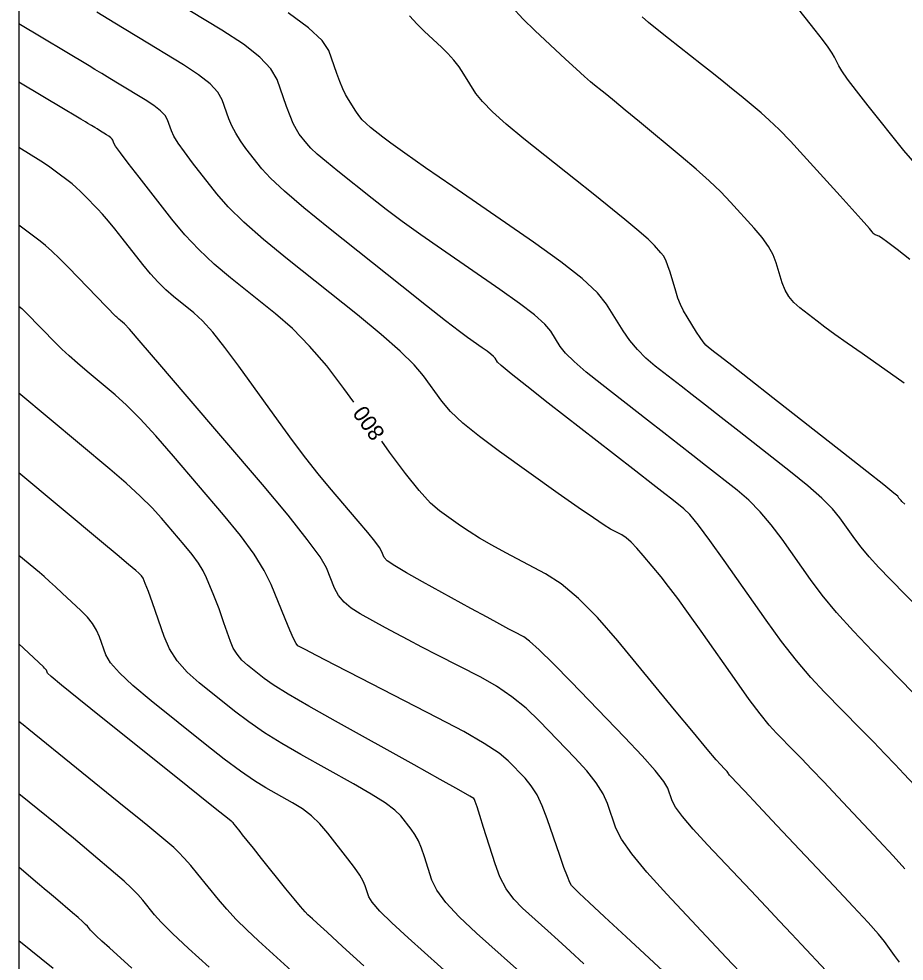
# Model space of a CAD drawing. Extents: x 2082232 to 2083549, y 592624 to 593832.
# Drawn here: x 2082231.79 to 2082270.56, y 593384.11 to 593425.39 of the extents above; entities that cross this region are included whole.
import ezdxf

# ---------------------------------------------------------------- set-up
doc = ezdxf.new("R2010")
doc.units = 0
for name, color, linetype in [('DT_X_Contour_Major', 7, 'Continuous'), ('DT_X_Contour_Minor', 7, 'Continuous'), ('DT_X_TIN_Hull', 7, 'Continuous')]:
    doc.layers.add(name, color=color, linetype=linetype)

msp = doc.modelspace()

# ---------------------------------------------------------------- linework, layer by layer
at = {"layer": 'DT_X_Contour_Major'}
for points in [[(2082270.584, 593404.122), (2082270.465, 593404.244), (2082270.423, 593404.288), (2082270.387, 593404.327), (2082270.357, 593404.363), (2082270.334, 593404.394), (2082270.279, 593404.472), (2082270.116, 593404.612), (2082269.666, 593404.972), (2082268.931, 593405.553), (2082267.91, 593406.355), (2082264.806, 593408.788), (2082263.775, 593409.597), (2082263.008, 593410.197), (2082262.507, 593410.59), (2082262.27, 593410.775), (2082261.993, 593410.991), (2082261.882, 593411.094), (2082261.758, 593411.24), (2082261.621, 593411.428), (2082261.471, 593411.66), (2082261.052, 593412.335), (2082260.903, 593412.596), (2082260.77, 593412.87), (2082260.654, 593413.159), (2082260.554, 593413.462), (2082260.309, 593414.288), (2082260.215, 593414.574), (2082260.117, 593414.812), (2082260.016, 593415.003), (2082259.91, 593415.145), (2082259.623, 593415.462), (2082259.5, 593415.59), (2082259.346, 593415.736), (2082259.161, 593415.901), (2082258.945, 593416.084), (2082258.327, 593416.596), (2082258.018, 593416.849), (2082257.555, 593417.223), (2082256.937, 593417.718), (2082256.166, 593418.334), (2082253.902, 593420.138), (2082253.134, 593420.77), (2082252.529, 593421.312), (2082252.087, 593421.763), (2082251.807, 593422.125), (2082251.278, 593422.97), (2082251.068, 593423.281), (2082250.837, 593423.579), (2082250.582, 593423.865), (2082250.306, 593424.138), (2082249.539, 593424.851), (2082249.236, 593425.154), (2082248.902, 593425.526)], [(2082246.452, 593408.59), (2082246.019, 593409.192), (2082245.269, 593410.18), (2082244.522, 593411.055), (2082243.777, 593411.816), (2082243.034, 593412.465), (2082241.055, 593414.043), (2082240.339, 593414.648), (2082239.673, 593415.277), (2082239.058, 593415.932), (2082238.493, 593416.612), (2082237.055, 593418.459), (2082236.581, 593419.072), (2082236.238, 593419.523), (2082236.025, 593419.813), (2082235.942, 593419.942), (2082235.896, 593420.073), (2082235.867, 593420.124), (2082235.813, 593420.181), (2082235.734, 593420.243), (2082235.631, 593420.311), (2082235.323, 593420.498), (2082235.214, 593420.564), (2082235.119, 593420.622), (2082235.038, 593420.671), (2082234.97, 593420.712), (2082234.807, 593420.81), (2082234.699, 593420.874), (2082234.497, 593420.995), (2082234.203, 593421.171), (2082233.815, 593421.403), (2082231.787, 593422.616)], [(2082270.363, 593384.065), (2082270.137, 593384.36), (2082269.698, 593384.96), (2082269.436, 593385.281), (2082268.982, 593385.795), (2082268.334, 593386.5), (2082267.492, 593387.398), (2082264.991, 593390.049), (2082264.166, 593390.924), (2082263.565, 593391.561), (2082263.19, 593391.958), (2082263.04, 593392.118), (2082262.939, 593392.225), (2082262.906, 593392.261), (2082262.881, 593392.291), (2082262.864, 593392.313), (2082262.856, 593392.327), (2082262.846, 593392.357), (2082262.834, 593392.376), (2082262.806, 593392.41), (2082262.76, 593392.459), (2082262.699, 593392.524), (2082262.511, 593392.718), (2082262.334, 593392.923), (2082261.94, 593393.391), (2082261.331, 593394.124), (2082260.507, 593395.121), (2082258.021, 593398.132), (2082257.124, 593399.163), (2082256.296, 593399.998), (2082255.539, 593400.637), (2082254.852, 593401.08), (2082253.114, 593402.001), (2082252.501, 593402.333), (2082251.965, 593402.641), (2082251.506, 593402.923), (2082251.124, 593403.18), (2082250.209, 593403.831), (2082249.815, 593404.175), (2082249.319, 593404.719), (2082248.721, 593405.463), (2082248.021, 593406.408), (2082247.678, 593406.885)], [(2082254.117, 593383.283), (2082251.833, 593385.333), (2082251.068, 593386.054), (2082250.487, 593386.68), (2082250.09, 593387.211), (2082249.876, 593387.647), (2082249.552, 593388.683), (2082249.424, 593389.05), (2082249.284, 593389.374), (2082249.132, 593389.656), (2082248.968, 593389.894), (2082248.515, 593390.474), (2082248.257, 593390.725), (2082247.826, 593391.041), (2082247.221, 593391.424), (2082246.441, 593391.873), (2082244.13, 593393.159), (2082243.299, 593393.639), (2082242.54, 593394.115), (2082241.853, 593394.586), (2082241.237, 593395.053), (2082239.691, 593396.292), (2082239.16, 593396.768), (2082238.726, 593397.266), (2082238.388, 593397.786), (2082238.148, 593398.329), (2082237.636, 593399.805), (2082237.462, 593400.294), (2082237.326, 593400.656), (2082237.226, 593400.889), (2082237.163, 593400.994), (2082237.046, 593401.104), (2082236.91, 593401.221), (2082236.592, 593401.489), (2082236.091, 593401.908), (2082235.406, 593402.479), (2082231.787, 593405.496)], [(2082236.733, 593383.805), (2082235.753, 593384.687), (2082235.426, 593384.984), (2082235.178, 593385.213), (2082235.009, 593385.376), (2082234.92, 593385.47), (2082234.789, 593385.633), (2082234.711, 593385.716), (2082234.576, 593385.843), (2082234.384, 593386.014), (2082234.134, 593386.228), (2082233.392, 593386.858), (2082233.129, 593387.081), (2082232.896, 593387.279), (2082232.693, 593387.451), (2082232.521, 593387.597), (2082231.787, 593388.22)]]:
    msp.add_lwpolyline(points, dxfattribs=at)
at = {"layer": 'DT_X_Contour_Minor'}
for points in [[(2082271.56, 593395.252), (2082269.177, 593397.682), (2082268.337, 593398.563), (2082267.603, 593399.381), (2082266.977, 593400.136), (2082266.458, 593400.83), (2082265.215, 593402.597), (2082264.742, 593403.227), (2082264.256, 593403.794), (2082263.757, 593404.298), (2082263.243, 593404.737), (2082261.857, 593405.824), (2082261.308, 593406.254), (2082260.701, 593406.728), (2082260.037, 593407.246), (2082259.316, 593407.808), (2082257.314, 593409.367), (2082256.638, 593409.91), (2082256.11, 593410.37), (2082255.731, 593410.746), (2082255.501, 593411.039), (2082255.086, 593411.708), (2082254.83, 593412.01), (2082254.373, 593412.415), (2082253.716, 593412.923), (2082252.857, 593413.534), (2082250.301, 593415.298), (2082249.392, 593415.933), (2082248.582, 593416.515), (2082247.871, 593417.043), (2082247.26, 593417.518), (2082245.762, 593418.713), (2082245.255, 593419.125), (2082244.858, 593419.464), (2082244.571, 593419.73), (2082244.394, 593419.923), (2082244.069, 593420.341), (2082243.942, 593420.534), (2082243.807, 593420.799), (2082243.664, 593421.136), (2082243.512, 593421.544), (2082243.097, 593422.729), (2082242.829, 593423.198), (2082242.337, 593423.716), (2082241.621, 593424.282), (2082240.682, 593424.897), (2082237.878, 593426.603)], [(2082271.516, 593391.292), (2082270.553, 593392.312), (2082270.164, 593392.723), (2082269.716, 593393.187), (2082269.212, 593393.707), (2082268.651, 593394.281), (2082267.077, 593395.886), (2082266.474, 593396.535), (2082265.847, 593397.278), (2082265.196, 593398.116), (2082264.519, 593399.048), (2082262.683, 593401.659), (2082262.056, 593402.535), (2082261.551, 593403.205), (2082261.169, 593403.67), (2082260.91, 593403.928), (2082260.382, 593404.342), (2082260.074, 593404.582), (2082259.548, 593404.993), (2082258.803, 593405.574), (2082257.838, 593406.325), (2082254.974, 593408.555), (2082254.03, 593409.295), (2082253.344, 593409.841), (2082252.917, 593410.195), (2082252.748, 593410.354), (2082252.644, 593410.523), (2082252.579, 593410.599), (2082252.465, 593410.701), (2082252.299, 593410.829), (2082252.083, 593410.982), (2082251.44, 593411.426), (2082251.079, 593411.691), (2082250.478, 593412.155), (2082249.636, 593412.816), (2082248.555, 593413.676), (2082245.352, 593416.232), (2082244.268, 593417.112), (2082243.42, 593417.837), (2082242.806, 593418.406), (2082242.427, 593418.819), (2082241.731, 593419.714), (2082241.489, 593420.047), (2082241.284, 593420.374), (2082241.118, 593420.695), (2082240.989, 593421.01), (2082240.697, 593421.844), (2082240.508, 593422.174), (2082240.162, 593422.538), (2082239.659, 593422.936), (2082238.998, 593423.369), (2082237.026, 593424.568), (2082236.33, 593424.991), (2082235.721, 593425.36), (2082235.199, 593425.675)], [(2082270.567, 593409.421), (2082268.715, 593410.722), (2082268.071, 593411.176), (2082267.53, 593411.564), (2082267.09, 593411.884), (2082266.753, 593412.138), (2082265.989, 593412.724), (2082265.727, 593412.958), (2082265.511, 593413.219), (2082265.343, 593413.508), (2082265.221, 593413.824), (2082264.961, 593414.703), (2082264.826, 593415.045), (2082264.62, 593415.412), (2082264.341, 593415.803), (2082263.989, 593416.219), (2082262.954, 593417.361), (2082262.528, 593417.807), (2082262.028, 593418.289), (2082261.452, 593418.806), (2082260.802, 593419.359), (2082258.967, 593420.881), (2082258.349, 593421.393), (2082257.872, 593421.787), (2082257.535, 593422.063), (2082257.338, 593422.221), (2082257.002, 593422.484), (2082256.828, 593422.63), (2082256.559, 593422.868), (2082256.195, 593423.199), (2082255.736, 593423.624), (2082254.385, 593424.879), (2082253.877, 593425.378), (2082253.367, 593425.931)], [(2082271.131, 593418.944), (2082270.54, 593419.617), (2082268.992, 593421.571), (2082268.476, 593422.23), (2082268.087, 593422.742), (2082267.826, 593423.107), (2082267.693, 593423.325), (2082267.507, 593423.71), (2082267.403, 593423.892), (2082267.227, 593424.149), (2082266.981, 593424.48), (2082266.665, 593424.887), (2082265.726, 593426.07)], [(2082271.361, 593399.393), (2082269.945, 593400.837), (2082269.449, 593401.354), (2082269.026, 593401.822), (2082268.675, 593402.242), (2082268.396, 593402.612), (2082267.747, 593403.534), (2082267.429, 593403.92), (2082266.961, 593404.383), (2082266.344, 593404.925), (2082265.577, 593405.546), (2082263.332, 593407.306), (2082262.541, 593407.925), (2082261.855, 593408.463), (2082261.272, 593408.918), (2082260.793, 593409.292), (2082259.653, 593410.179), (2082259.245, 593410.525), (2082258.876, 593410.898), (2082258.546, 593411.297), (2082258.254, 593411.723), (2082257.528, 593412.893), (2082257.124, 593413.392), (2082256.457, 593414.01), (2082255.525, 593414.747), (2082254.33, 593415.603), (2082250.79, 593418.046), (2082249.604, 593418.868), (2082248.698, 593419.501), (2082248.073, 593419.945), (2082247.73, 593420.202), (2082247.188, 593420.633), (2082246.995, 593420.799), (2082246.823, 593420.972), (2082246.672, 593421.153), (2082246.541, 593421.341), (2082246.221, 593421.853), (2082246.099, 593422.068), (2082245.974, 593422.33), (2082245.846, 593422.639), (2082245.714, 593422.996), (2082245.359, 593424.008), (2082245.072, 593424.444), (2082244.477, 593424.993), (2082243.575, 593425.653)], [(2082270.814, 593414.852), (2082270.253, 593415.282), (2082269.839, 593415.594), (2082269.573, 593415.788), (2082269.455, 593415.863), (2082269.338, 593415.908), (2082269.294, 593415.929), (2082269.251, 593415.961), (2082269.207, 593416.001), (2082269.163, 593416.052), (2082269.046, 593416.2), (2082268.932, 593416.331), (2082268.679, 593416.615), (2082268.287, 593417.05), (2082267.755, 593417.638), (2082266.151, 593419.408), (2082265.584, 593420.023), (2082265.085, 593420.539), (2082264.656, 593420.957), (2082264.297, 593421.276), (2082263.429, 593421.996), (2082263.076, 593422.285), (2082262.668, 593422.614), (2082262.206, 593422.982), (2082261.689, 593423.389), (2082260.237, 593424.526), (2082259.747, 593424.917), (2082259.364, 593425.236), (2082259.091, 593425.484)], [(2082270.596, 593388.148), (2082270.078, 593388.727), (2082269.457, 593389.396), (2082267.661, 593391.299), (2082267.036, 593391.96), (2082266.507, 593392.516), (2082266.076, 593392.966), (2082265.741, 593393.311), (2082264.977, 593394.09), (2082264.653, 593394.45), (2082264.254, 593394.945), (2082263.78, 593395.576), (2082263.231, 593396.342), (2082261.667, 593398.565), (2082261.118, 593399.339), (2082260.642, 593399.992), (2082260.24, 593400.526), (2082259.912, 593400.939), (2082259.135, 593401.88), (2082258.858, 593402.2), (2082258.608, 593402.457), (2082258.385, 593402.649), (2082258.19, 593402.777), (2082257.707, 593403.033), (2082257.427, 593403.203), (2082256.952, 593403.521), (2082256.28, 593403.986), (2082255.413, 593404.6), (2082252.837, 593406.433), (2082251.955, 593407.087), (2082251.239, 593407.673), (2082250.689, 593408.191), (2082250.306, 593408.641), (2082249.507, 593409.753), (2082249.102, 593410.232), (2082248.484, 593410.835), (2082247.655, 593411.563), (2082246.614, 593412.416), (2082243.555, 593414.857), (2082242.501, 593415.722), (2082241.634, 593416.487), (2082240.954, 593417.152), (2082240.46, 593417.716), (2082239.393, 593419.087), (2082239.035, 593419.559), (2082238.761, 593419.948), (2082238.571, 593420.254), (2082238.466, 593420.476), (2082238.296, 593420.958), (2082238.188, 593421.149), (2082237.988, 593421.359), (2082237.697, 593421.59), (2082237.315, 593421.84), (2082236.175, 593422.533), (2082235.772, 593422.777), (2082235.42, 593422.991), (2082235.118, 593423.173), (2082234.867, 593423.324), (2082231.787, 593425.167)], [(2082267.13, 593383.703), (2082266.06, 593384.838), (2082265.62, 593385.304), (2082265.103, 593385.853), (2082264.511, 593386.484), (2082263.841, 593387.197), (2082261.953, 593389.208), (2082261.325, 593389.893), (2082260.856, 593390.443), (2082260.546, 593390.855), (2082260.396, 593391.131), (2082260.207, 593391.685), (2082260.035, 593391.98), (2082259.662, 593392.451), (2082259.088, 593393.096), (2082258.312, 593393.916), (2082255.974, 593396.337), (2082255.188, 593397.141), (2082254.581, 593397.739), (2082254.153, 593398.13), (2082253.905, 593398.315), (2082253.484, 593398.532), (2082253.246, 593398.657), (2082252.849, 593398.87), (2082252.294, 593399.172), (2082251.579, 593399.562), (2082249.46, 593400.719), (2082248.76, 593401.112), (2082248.247, 593401.422), (2082247.923, 593401.649), (2082247.787, 593401.794), (2082247.676, 593402.07), (2082247.58, 593402.23), (2082247.377, 593402.502), (2082247.067, 593402.886), (2082246.649, 593403.383), (2082245.392, 593404.858), (2082244.899, 593405.454), (2082244.361, 593406.138), (2082243.779, 593406.909), (2082243.153, 593407.767), (2082241.423, 593410.172), (2082240.814, 593410.995), (2082240.282, 593411.659), (2082239.829, 593412.166), (2082239.453, 593412.513), (2082238.556, 593413.229), (2082238.22, 593413.518), (2082237.883, 593413.848), (2082237.547, 593414.218), (2082237.211, 593414.629), (2082236.315, 593415.78), (2082235.996, 593416.184), (2082235.709, 593416.532), (2082235.455, 593416.826), (2082235.235, 593417.064), (2082234.69, 593417.625), (2082234.49, 593417.825), (2082234.299, 593418.003), (2082234.117, 593418.161), (2082233.944, 593418.298), (2082233.494, 593418.635), (2082233.321, 593418.762), (2082233.139, 593418.89), (2082232.947, 593419.019), (2082232.746, 593419.149), (2082231.787, 593419.757)], [(2082263.654, 593383.332), (2082262.772, 593384.268), (2082260.166, 593387.044), (2082259.294, 593388.006), (2082258.631, 593388.808), (2082258.178, 593389.451), (2082257.935, 593389.935), (2082257.567, 593391.014), (2082257.374, 593391.442), (2082257.071, 593391.919), (2082256.659, 593392.444), (2082256.136, 593393.018), (2082254.597, 593394.613), (2082254.002, 593395.182), (2082253.375, 593395.693), (2082252.713, 593396.146), (2082252.017, 593396.541), (2082250.118, 593397.518), (2082249.442, 593397.867), (2082248.839, 593398.182), (2082248.309, 593398.463), (2082247.852, 593398.71), (2082246.73, 593399.322), (2082246.344, 593399.565), (2082246.031, 593399.834), (2082245.788, 593400.129), (2082245.618, 593400.45), (2082245.257, 593401.341), (2082244.981, 593401.819), (2082244.421, 593402.585), (2082243.579, 593403.639), (2082242.454, 593404.981), (2082239.077, 593408.943), (2082237.961, 593410.25), (2082237.145, 593411.199), (2082236.628, 593411.791), (2082236.412, 593412.025), (2082236.234, 593412.173), (2082236.172, 593412.226), (2082236.118, 593412.273), (2082236.073, 593412.315), (2082236.036, 593412.352), (2082233.955, 593414.495), (2082233.568, 593414.887), (2082233.235, 593415.209), (2082232.954, 593415.463), (2082232.726, 593415.648), (2082231.787, 593416.352)], [(2082261.21, 593382.55), (2082258.38, 593385.173), (2082257.444, 593386.041), (2082256.76, 593386.679), (2082256.327, 593387.085), (2082256.146, 593387.26), (2082255.997, 593387.418), (2082255.923, 593387.545), (2082255.811, 593387.808), (2082255.662, 593388.206), (2082255.475, 593388.739), (2082254.928, 593390.342), (2082254.713, 593390.904), (2082254.481, 593391.388), (2082254.23, 593391.793), (2082253.961, 593392.12), (2082253.219, 593392.889), (2082252.817, 593393.222), (2082252.168, 593393.646), (2082251.272, 593394.161), (2082250.129, 593394.767), (2082246.752, 593396.504), (2082245.638, 593397.077), (2082244.829, 593397.493), (2082244.324, 593397.753), (2082244.125, 593397.857), (2082243.999, 593397.926), (2082243.929, 593398.019), (2082243.814, 593398.247), (2082243.654, 593398.609), (2082243.448, 593399.107), (2082242.839, 593400.612), (2082242.537, 593401.226), (2082242.087, 593401.939), (2082241.489, 593402.752), (2082240.744, 593403.663), (2082238.559, 593406.226), (2082237.785, 593407.115), (2082237.101, 593407.86), (2082236.508, 593408.459), (2082236.005, 593408.914), (2082234.783, 593409.934), (2082234.354, 593410.298), (2082233.984, 593410.624), (2082233.671, 593410.913), (2082233.416, 593411.164), (2082232.092, 593412.528), (2082232.037, 593412.583), (2082231.99, 593412.629), (2082231.951, 593412.664), (2082231.919, 593412.69), (2082231.787, 593412.789)], [(2082256.532, 593383.989), (2082255.933, 593384.539), (2082255.408, 593385.019), (2082254.956, 593385.427), (2082253.85, 593386.42), (2082253.463, 593386.821), (2082253.133, 593387.279), (2082252.86, 593387.793), (2082252.644, 593388.365), (2082252.142, 593389.965), (2082251.976, 593390.492), (2082251.854, 593390.873), (2082251.777, 593391.107), (2082251.743, 593391.194), (2082251.714, 593391.232), (2082251.542, 593391.335), (2082251.05, 593391.613), (2082250.238, 593392.069), (2082249.104, 593392.7), (2082245.655, 593394.619), (2082244.489, 593395.276), (2082243.579, 593395.807), (2082242.925, 593396.213), (2082242.527, 593396.492), (2082241.806, 593397.07), (2082241.556, 593397.298), (2082241.348, 593397.548), (2082241.18, 593397.82), (2082241.053, 593398.115), (2082240.77, 593398.931), (2082240.663, 593399.235), (2082240.553, 593399.534), (2082240.44, 593399.83), (2082240.324, 593400.122), (2082240.012, 593400.894), (2082239.863, 593401.202), (2082239.65, 593401.546), (2082239.373, 593401.928), (2082239.033, 593402.346), (2082238.041, 593403.51), (2082237.62, 593403.972), (2082237.103, 593404.483), (2082236.488, 593405.043), (2082235.777, 593405.653), (2082231.787, 593408.986)], [(2082250.99, 593383.193), (2082248.835, 593385.126), (2082248.122, 593385.783), (2082247.596, 593386.302), (2082247.258, 593386.685), (2082247.109, 593386.93), (2082246.961, 593387.401), (2082246.872, 593387.608), (2082246.714, 593387.876), (2082246.487, 593388.205), (2082246.193, 593388.595), (2082245.315, 593389.716), (2082244.973, 593390.115), (2082244.602, 593390.469), (2082244.204, 593390.78), (2082243.778, 593391.047), (2082242.605, 593391.699), (2082242.109, 593392.003), (2082241.501, 593392.423), (2082240.78, 593392.96), (2082239.947, 593393.614), (2082237.576, 593395.514), (2082236.786, 593396.175), (2082236.192, 593396.73), (2082235.795, 593397.181), (2082235.594, 593397.527), (2082235.323, 593398.309), (2082235.195, 593398.602), (2082235.017, 593398.893), (2082234.787, 593399.182), (2082234.505, 593399.469), (2082233.687, 593400.234), (2082233.394, 593400.504), (2082233.13, 593400.744), (2082232.894, 593400.952), (2082232.687, 593401.128), (2082231.787, 593401.878)], [(2082246.892, 593383.897), (2082245.969, 593384.745), (2082245.288, 593385.37), (2082244.848, 593385.773), (2082244.65, 593385.954), (2082244.443, 593386.14), (2082244.325, 593386.264), (2082244.126, 593386.494), (2082243.847, 593386.831), (2082243.486, 593387.276), (2082242.417, 593388.603), (2082242.057, 593389.05), (2082241.78, 593389.395), (2082241.585, 593389.639), (2082241.473, 593389.781), (2082241.283, 593390.024), (2082241.219, 593390.104), (2082241.17, 593390.164), (2082241.135, 593390.202), (2082241.115, 593390.22), (2082241.08, 593390.239), (2082240.919, 593390.366), (2082240.461, 593390.73), (2082239.707, 593391.334), (2082238.657, 593392.175), (2082235.461, 593394.737), (2082234.411, 593395.581), (2082233.658, 593396.194), (2082233.201, 593396.575), (2082233.041, 593396.725), (2082233.01, 593396.814), (2082232.992, 593396.851), (2082232.961, 593396.894), (2082232.917, 593396.944), (2082232.86, 593397), (2082231.787, 593398.001)], [(2082243.734, 593383.686), (2082242.285, 593384.991), (2082241.767, 593385.471), (2082241.302, 593385.933), (2082240.889, 593386.377), (2082240.527, 593386.802), (2082239.633, 593387.913), (2082239.315, 593388.298), (2082239.032, 593388.621), (2082238.783, 593388.882), (2082238.568, 593389.08), (2082238.042, 593389.527), (2082237.791, 593389.737), (2082237.434, 593390.031), (2082236.97, 593390.41), (2082236.399, 593390.873), (2082232.224, 593394.253), (2082231.969, 593394.46), (2082231.917, 593394.502), (2082231.787, 593394.606)], [(2082240.127, 593383.842), (2082239.22, 593384.666), (2082238.517, 593385.324), (2082238.018, 593385.814), (2082237.724, 593386.136), (2082237.211, 593386.773), (2082236.993, 593387.024), (2082236.722, 593387.301), (2082236.4, 593387.603), (2082236.025, 593387.931), (2082234.956, 593388.838), (2082234.561, 593389.171), (2082234.178, 593389.492), (2082233.806, 593389.799), (2082233.445, 593390.093), (2082231.787, 593391.436)], [(2082233.297, 593383.783), (2082231.787, 593384.998)]]:
    msp.add_lwpolyline(points, dxfattribs=at)
at = {"layer": 'DT_X_TIN_Hull'}
msp.add_lwpolyline([(2082231.787, 593431.071), (2082231.787, 593421.23), (2082231.787, 593418.254), (2082231.787, 593412.207), (2082231.787, 593409.223), (2082231.787, 593406.329), (2082231.787, 593400.681), (2082231.787, 593397.164), (2082231.787, 593396.53), (2082231.787, 593393.915), (2082231.787, 593389.285), (2082231.787, 593387.453), (2082231.787, 593385.022), (2082231.787, 593378.886)], dxfattribs=at)

# ---------------------------------------------------------------- texts
at = {"layer": 'DT_X_Contour_Major'}
msp.add_text('800', height=0.7, rotation=125.7184, dxfattribs=at).set_placement((2082247.851, 593407.244))

doc.saveas('drawing.dxf')
